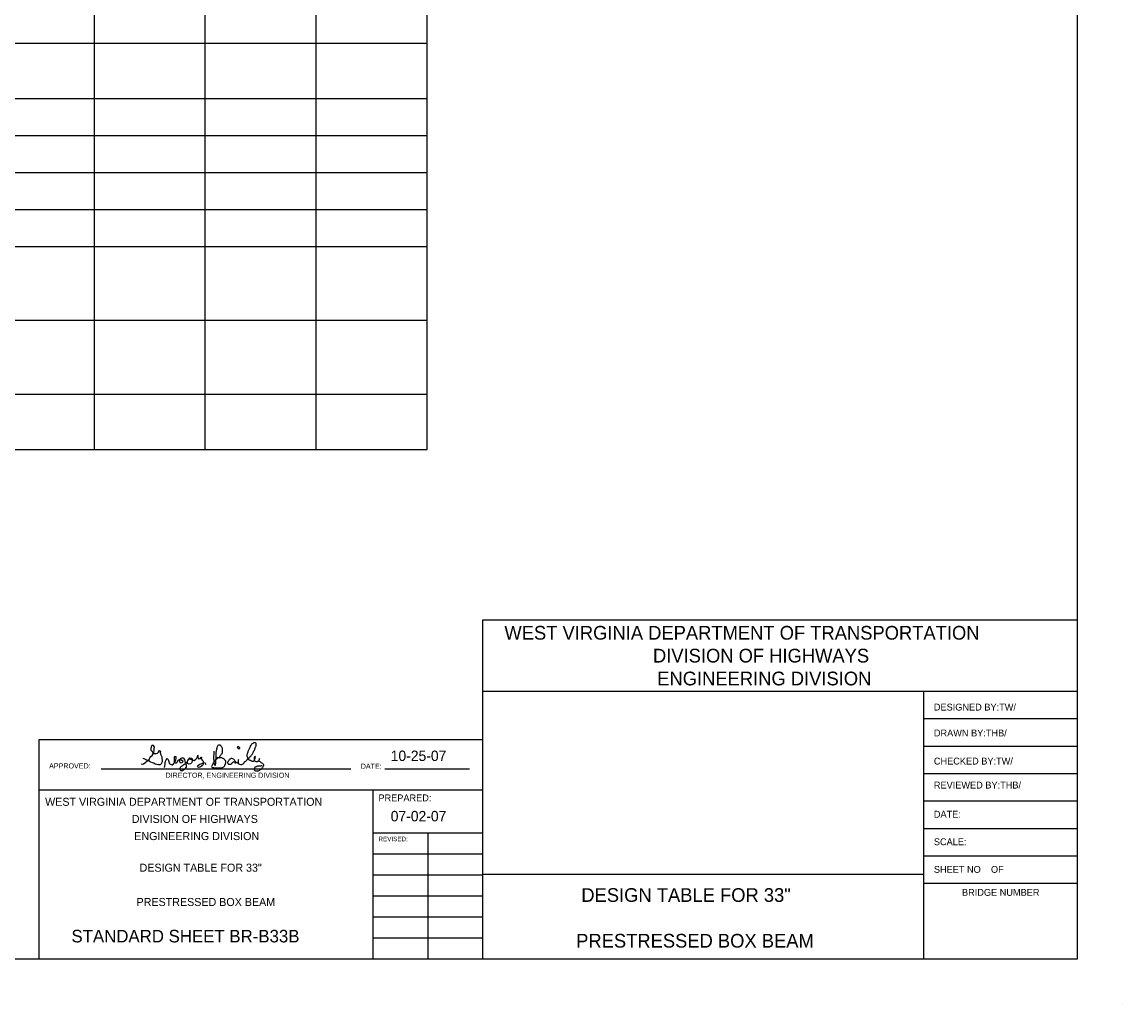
# Model space of a CAD drawing. Extents: x 762.3 to 790.4, y -1210.3 to -1192.2.
# Drawn here: x 780.44 to 790.37, y -1210.35 to -1201.48 of the extents above; entities that cross this region are included whole.
import ezdxf

# ---------------------------------------------------------------- set-up
doc = ezdxf.new("R2010")
doc.units = 0
for name, color, linetype in [('CURBLINE', 7, 'Continuous'), ('Default', 7, 'Continuous'), ('Level 1', 7, 'Continuous')]:
    doc.layers.add(name, color=color, linetype=linetype)

msp = doc.modelspace()

# ---------------------------------------------------------------- linework, layer by layer
at = {"layer": 'CURBLINE'}
msp.add_line((789.9542, -1206.8764), (784.5917, -1206.8755), dxfattribs=at)
at = {"layer": 'Default'}
for p, q in [((789.9542, -1192.6096), (789.9542, -1209.9346)), ((784.0909, -1205.3356), (784.0909, -1193.1689)), ((781.0909, -1205.3356), (781.0909, -1193.6689)), ((782.0909, -1205.3356), (782.0909, -1193.6689)), ((783.0909, -1205.3356), (783.0909, -1193.6689)), ((764.5075, -1201.6689), (784.0909, -1201.6689)), ((764.5075, -1202.1689), (784.0909, -1202.1689)), ((766.2575, -1202.5023), (784.0909, -1202.5023)), ((766.2575, -1202.8356), (784.0909, -1202.8356)), ((764.5075, -1203.1689), (784.0909, -1203.1689)), ((766.2575, -1203.5023), (784.0909, -1203.5023)), ((766.2575, -1204.1689), (784.0909, -1204.1689)), ((764.5075, -1204.8356), (784.0909, -1204.8356)), ((764.5075, -1205.3356), (784.0909, -1205.3356)), ((784.5917, -1206.8755), (784.5917, -1209.9346)), ((788.5682, -1207.519), (784.5917, -1207.519)), ((788.5682, -1207.519), (788.5682, -1209.9346)), ((789.9542, -1207.519), (788.5682, -1207.519)), ((789.9542, -1207.7665), (788.5682, -1207.7665)), ((784.5917, -1207.9546), (780.5905, -1207.9546)), ((780.5905, -1207.9546), (780.5905, -1209.9346)), ((789.9542, -1208.014), (788.5682, -1208.014)), ((781.152, -1208.2157), (783.4022, -1208.2157)), ((783.7105, -1208.2157), (784.4725, -1208.2157)), ((789.9542, -1208.2615), (788.5682, -1208.2615)), ((783.6017, -1208.4083), (780.5905, -1208.4083)), ((783.6017, -1208.4083), (783.6017, -1209.9346)), ((784.5917, -1208.4083), (783.6017, -1208.4083)), ((789.9542, -1208.509), (788.5682, -1208.509)), ((784.5917, -1208.7961), (783.6017, -1208.7961)), ((784.0967, -1208.7961), (784.0967, -1209.9346)), ((789.9542, -1208.7565), (788.5682, -1208.7565)), ((784.5917, -1208.9858), (783.6017, -1208.9858)), ((789.9542, -1209.004), (788.5682, -1209.004)), ((784.5917, -1209.1756), (783.6017, -1209.1756)), ((788.5682, -1209.169), (784.5917, -1209.169)), ((789.9542, -1209.2515), (788.5682, -1209.2515)), ((784.5917, -1209.3653), (783.6017, -1209.3653)), ((784.5917, -1209.5551), (783.6017, -1209.5551)), ((784.5917, -1209.7448), (783.6017, -1209.7448)), ((789.9542, -1209.9346), (763.5542, -1209.9346)), ((790.3667, -1210.3471), (790.3667, -1210.3471))]:
    msp.add_line(p, q, dxfattribs=at)
at = {"layer": 'Level 1'}
for points in [[(781.5129, -1208.1703), (781.528, -1208.1728), (781.5377, -1208.1681), (781.5506, -1208.1603), (781.5606, -1208.1502), (781.5732, -1208.1427), (781.5845, -1208.1314), (781.5908, -1208.1163), (781.5996, -1208.105), (781.6109, -1208.0949), (781.6197, -1208.0824), (781.626, -1208.0686), (781.6285, -1208.0522), (781.631, -1208.0372), (781.6322, -1208.0221), (781.6234, -1208.007), (781.6096, -1208.007), (781.6021, -1208.0183), (781.5996, -1208.0321), (781.5996, -1208.0472), (781.6096, -1208.0573), (781.6184, -1208.0698), (781.631, -1208.0774), (781.6473, -1208.0786), (781.6611, -1208.0761), (781.6699, -1208.0648), (781.6787, -1208.051), (781.6863, -1208.056), (781.6837, -1208.0698), (781.6875, -1208.0836), (781.6925, -1208.0962), (781.6976, -1208.1088), (781.7001, -1208.1238), (781.7026, -1208.1389), (781.7026, -1208.154), (781.6938, -1208.1703), (781.6837, -1208.1804), (781.6674, -1208.1804), (781.6548, -1208.1769), (781.6398, -1208.1728), (781.6272, -1208.1653), (781.6147, -1208.1621), (781.6008, -1208.1552), (781.587, -1208.1502), (781.5757, -1208.1427), (781.5632, -1208.1377), (781.5506, -1208.1326), (781.5393, -1208.1251), (781.5267, -1208.1226)], [(782.167, -1208.0573), (782.1676, -1208.0642), (782.1676, -1208.0711), (782.1676, -1208.078), (782.1676, -1208.0855), (782.1664, -1208.0924), (782.1651, -1208.0993), (782.1651, -1208.1063), (782.1651, -1208.1132), (782.1651, -1208.1201), (782.1658, -1208.127), (782.1664, -1208.1339), (782.1664, -1208.1408), (782.167, -1208.1477), (782.1683, -1208.1546), (782.1689, -1208.1621), (782.1695, -1208.1691), (782.1714, -1208.176), (782.1758, -1208.181), (782.1796, -1208.1866), (782.1815, -1208.1797), (782.184, -1208.1735), (782.1859, -1208.1665), (782.1865, -1208.1596), (782.1865, -1208.1527), (782.1865, -1208.1458), (782.1871, -1208.1389), (782.1871, -1208.132), (782.1877, -1208.1251), (782.1884, -1208.1182), (782.189, -1208.1113), (782.189, -1208.1044), (782.189, -1208.0975), (782.189, -1208.0906), (782.189, -1208.0836), (782.189, -1208.0767), (782.189, -1208.0698), (782.1896, -1208.0629), (782.1909, -1208.056), (782.1921, -1208.0485), (782.194, -1208.0416), (782.1959, -1208.0347), (782.1965, -1208.0277), (782.1991, -1208.0215), (782.2016, -1208.0152), (782.2041, -1208.0089), (782.2078, -1208.0026), (782.2141, -1208.0001), (782.221, -1208.0007), (782.2279, -1208.0026), (782.2323, -1208.0076), (782.2355, -1208.0139), (782.2392, -1208.0196), (782.2424, -1208.0259), (782.2436, -1208.0328), (782.2443, -1208.0397), (782.2443, -1208.0466), (782.2443, -1208.0535), (782.2443, -1208.0604), (782.2443, -1208.0673), (782.243, -1208.0742), (782.2392, -1208.0799), (782.2342, -1208.0843), (782.2298, -1208.0893), (782.2273, -1208.0956), (782.2235, -1208.1012), (782.2198, -1208.1069), (782.2173, -1208.1132), (782.2116, -1208.1169), (782.2053, -1208.1201), (782.1997, -1208.1245), (782.1934, -1208.1282), (782.1884, -1208.1326), (782.1833, -1208.1377), (782.1796, -1208.1433), (782.1746, -1208.1477), (782.1708, -1208.1534), (782.167, -1208.159), (782.162, -1208.1647), (782.1582, -1208.1703), (782.1557, -1208.1766), (782.1519, -1208.1822), (782.1494, -1208.1885), (782.1482, -1208.1954), (782.1507, -1208.2017), (782.157, -1208.2042), (782.1639, -1208.2049), (782.1708, -1208.2067), (782.1777, -1208.208), (782.1846, -1208.2086), (782.1915, -1208.2086), (782.1991, -1208.2086), (782.206, -1208.2086), (782.2129, -1208.2086), (782.2198, -1208.2086), (782.2267, -1208.2086), (782.2336, -1208.2086), (782.2405, -1208.2086), (782.2455, -1208.2036), (782.2518, -1208.2011), (782.2575, -1208.1973), (782.2631, -1208.1923), (782.2656, -1208.186), (782.2681, -1208.1797), (782.2719, -1208.1741), (782.2744, -1208.1678), (782.2763, -1208.1609), (782.2776, -1208.154), (782.2776, -1208.1471), (782.2732, -1208.142), (782.2681, -1208.1377), (782.2631, -1208.1326), (782.2587, -1208.127), (782.2524, -1208.1232), (782.2462, -1208.1194), (782.2392, -1208.1182), (782.2323, -1208.1169), (782.2254, -1208.1157), (782.2179, -1208.1157), (782.2104, -1208.1157), (782.2034, -1208.1157), (782.1965, -1208.1144), (782.1965, -1208.1144)], [(782.3824, -1208.0208), (782.3824, -1208.0277), (782.3875, -1208.0321), (782.3944, -1208.034), (782.4013, -1208.0334), (782.4025, -1208.0265), (782.3975, -1208.0221), (782.3925, -1208.0171), (782.3856, -1208.0171), (782.3793, -1208.0196), (782.3793, -1208.024)], [(782.4829, -1208.1238), (782.4867, -1208.1182), (782.4905, -1208.1125), (782.4942, -1208.1069), (782.4986, -1208.1019), (782.5043, -1208.0981), (782.5087, -1208.0931), (782.5124, -1208.0868), (782.5156, -1208.0805), (782.52, -1208.0742), (782.5238, -1208.0679), (782.5263, -1208.0617), (782.53, -1208.0548), (782.5332, -1208.0478), (782.5363, -1208.0409), (782.5388, -1208.0347), (782.5413, -1208.0284), (782.5438, -1208.0221), (782.5457, -1208.0152), (782.5482, -1208.0089), (782.5495, -1208.002), (782.5508, -1207.9951), (782.5495, -1207.9882), (782.5451, -1207.9832), (782.5388, -1207.9806), (782.5319, -1207.9794), (782.5256, -1207.9832), (782.52, -1207.9869), (782.5137, -1207.9894), (782.5087, -1207.9938), (782.5049, -1207.9995), (782.5011, -1208.0051), (782.4961, -1208.0102), (782.4949, -1208.0171), (782.4923, -1208.0233), (782.4898, -1208.0296), (782.4861, -1208.0353), (782.4836, -1208.0416), (782.4798, -1208.0472), (782.4785, -1208.0541), (782.4748, -1208.0598), (782.4735, -1208.0667), (782.471, -1208.0736), (782.4685, -1208.0805), (782.466, -1208.0868), (782.466, -1208.0937), (782.466, -1208.1006), (782.4672, -1208.1075), (782.4704, -1208.1138), (782.4729, -1208.1207), (782.476, -1208.127), (782.481, -1208.1314), (782.4873, -1208.1339), (782.493, -1208.1383), (782.4999, -1208.1395), (782.5062, -1208.1433), (782.5124, -1208.1458), (782.52, -1208.1464), (782.5269, -1208.1464), (782.5307, -1208.1408), (782.5344, -1208.1351), (782.5376, -1208.1282), (782.5401, -1208.1213), (782.5407, -1208.1144), (782.5426, -1208.1069), (782.5376, -1208.1025), (782.5351, -1208.1094), (782.5325, -1208.1157), (782.5325, -1208.1226), (782.5325, -1208.1295), (782.5325, -1208.1364), (782.5351, -1208.1433), (782.5413, -1208.1471), (782.5476, -1208.1496), (782.5545, -1208.1502), (782.5614, -1208.1502), (782.5677, -1208.1477), (782.5715, -1208.1414), (782.5759, -1208.1364), (782.579, -1208.1295), (782.5809, -1208.1226), (782.5778, -1208.1295), (782.5753, -1208.1358), (782.5727, -1208.142), (782.5753, -1208.1483), (782.5815, -1208.1515), (782.5878, -1208.1546), (782.5922, -1208.1596), (782.5991, -1208.1615), (782.606, -1208.164), (782.6104, -1208.1691), (782.6129, -1208.1753), (782.6154, -1208.1816), (782.6154, -1208.1885), (782.6142, -1208.1954), (782.6092, -1208.1998), (782.6054, -1208.2055), (782.6004, -1208.2111), (782.5966, -1208.2168), (782.5903, -1208.2212), (782.5853, -1208.2256), (782.579, -1208.2293), (782.5727, -1208.2331), (782.5671, -1208.2369), (782.5596, -1208.2375), (782.5526, -1208.2381), (782.5457, -1208.2381), (782.5395, -1208.2344), (782.5357, -1208.2287), (782.5344, -1208.2218), (782.5351, -1208.2149), (782.5369, -1208.208), (782.5407, -1208.2017), (782.5451, -1208.1967), (782.5514, -1208.1942), (782.5577, -1208.1917), (782.5646, -1208.1904), (782.5715, -1208.1904), (782.5784, -1208.1892), (782.5853, -1208.1892), (782.5922, -1208.1879), (782.5991, -1208.1866), (782.6029, -1208.1854)], [(781.723, -1208.2042), (781.7268, -1208.1898), (781.7286, -1208.176), (781.7305, -1208.1621), (781.733, -1208.1483), (781.7381, -1208.1345), (781.7462, -1208.1232), (781.7569, -1208.1314), (781.7632, -1208.1502), (781.7657, -1208.164), (781.7745, -1208.1741), (781.7927, -1208.181), (781.8028, -1208.1716), (781.8115, -1208.1603), (781.8197, -1208.1496), (781.8241, -1208.1364), (781.8291, -1208.1232), (781.8272, -1208.1094), (781.809, -1208.1069), (781.809, -1208.1207), (781.809, -1208.1345), (781.8109, -1208.1483), (781.8159, -1208.1615), (781.8316, -1208.1628), (781.8404, -1208.1527), (781.8448, -1208.1389), (781.8574, -1208.1333), (781.8712, -1208.1333), (781.8869, -1208.1452), (781.8825, -1208.1628), (781.8687, -1208.164), (781.8612, -1208.1527), (781.8618, -1208.1383), (781.8662, -1208.1245), (781.8781, -1208.1182), (781.8919, -1208.1157), (781.9032, -1208.132), (781.907, -1208.1458), (781.9108, -1208.159), (781.9152, -1208.1722), (781.9171, -1208.186), (781.9171, -1208.2005), (781.907, -1208.2174), (781.8963, -1208.2262), (781.8844, -1208.2337), (781.8706, -1208.2344), (781.8649, -1208.2155), (781.8687, -1208.2023), (781.8775, -1208.1923), (781.8872, -1208.1851), (781.8976, -1208.1766), (781.9145, -1208.1665), (781.9284, -1208.1521), (781.9332, -1208.1408), (781.9428, -1208.1282), (781.951, -1208.1176), (781.9692, -1208.1213), (781.9723, -1208.1351), (781.9723, -1208.149), (781.9673, -1208.1621), (781.9566, -1208.1703), (781.9434, -1208.1747), (781.9315, -1208.1684), (781.929, -1208.1552), (781.9321, -1208.142), (781.9403, -1208.1307), (781.9529, -1208.1257), (781.9711, -1208.1339), (781.9893, -1208.1402), (782.005, -1208.1301), (782.0131, -1208.1194), (782.0201, -1208.1069), (782.0251, -1208.0931), (782.0251, -1208.1), (782.0238, -1208.1138), (782.0295, -1208.1263), (782.0458, -1208.122), (782.0546, -1208.1113), (782.0559, -1208.1119), (782.054, -1208.1257), (782.0615, -1208.1383), (782.0716, -1208.1477), (782.0722, -1208.1615), (782.0722, -1208.1753), (782.0646, -1208.1866), (782.0546, -1208.1961), (782.0414, -1208.2017), (782.0282, -1208.2049), (782.0201, -1208.1942), (782.0289, -1208.1822), (782.0408, -1208.1741), (782.0546, -1208.1716), (782.0659, -1208.164), (782.0854, -1208.1603), (782.0954, -1208.176), (782.0967, -1208.1753)], [(782.363, -1208.1697), (782.3642, -1208.1628), (782.3642, -1208.1559), (782.3642, -1208.149), (782.3586, -1208.1439), (782.3536, -1208.1389), (782.3498, -1208.1333), (782.3441, -1208.1295), (782.3385, -1208.1257), (782.3322, -1208.1232), (782.3253, -1208.1232), (782.3184, -1208.1257), (782.3134, -1208.1301), (782.3077, -1208.1345), (782.3027, -1208.1389), (782.2989, -1208.1446), (782.2964, -1208.1508), (782.2926, -1208.1565), (782.2901, -1208.1628), (782.2945, -1208.1678), (782.2989, -1208.1728), (782.3064, -1208.1747), (782.3134, -1208.1747), (782.3203, -1208.1747), (782.3265, -1208.1722), (782.3309, -1208.1665), (782.3353, -1208.1615), (782.3397, -1208.1559), (782.346, -1208.1521), (782.3536, -1208.1521), (782.3611, -1208.1527), (782.3674, -1208.1552), (782.3736, -1208.1578), (782.3793, -1208.1615), (782.3862, -1208.1615), (782.3881, -1208.1546), (782.39, -1208.1477), (782.3906, -1208.1402), (782.3906, -1208.1333), (782.3881, -1208.1395), (782.3868, -1208.1464), (782.3868, -1208.1534), (782.3868, -1208.1603), (782.3875, -1208.1672), (782.3937, -1208.1703), (782.4, -1208.1741), (782.4069, -1208.176), (782.4138, -1208.1766), (782.4208, -1208.1766), (782.4277, -1208.1753), (782.4333, -1208.1716), (782.4371, -1208.1653), (782.4421, -1208.1609), (782.4459, -1208.1546), (782.4509, -1208.1502), (782.4566, -1208.1464), (782.4616, -1208.1414), (782.4666, -1208.1364), (782.4723, -1208.1326), (782.4779, -1208.1289), (782.4817, -1208.1238)]]:
    msp.add_lwpolyline(points, dxfattribs=at)

# ---------------------------------------------------------------- texts
at = {"layer": 'Default'}
for s, height, p in [('WEST VIRGINIA DEPARTMENT OF TRANSPORTATION', 0.12375, (784.7884, -1207.0508)), ('DIVISION OF HIGHWAYS', 0.12375, (786.1282, -1207.2571)), ('ENGINEERING DIVISION', 0.12375, (786.1667, -1207.4633)), ('DESIGNED BY:TW/', 0.061875, (788.6613, -1207.6904)), ('DRAWN BY:THB/', 0.061875, (788.6613, -1207.9241)), ('10-25-07', 0.09375, (783.7631, -1208.1456)), ('CHECKED BY:TW/', 0.061875, (788.6613, -1208.1776)), ('APPROVED:                                                  ', 0.046406, (780.6826, -1208.2129)), ('DATE:', 0.04641, (783.493, -1208.2157)), ('DIRECTOR, ENGINEERING DIVISION', 0.046406, (781.7318, -1208.2974)), ('REVIEWED BY:THB/', 0.061875, (788.6613, -1208.3941)), ('WEST VIRGINIA DEPARTMENT OF TRANSPORTATION', 0.072188, (780.6464, -1208.5498)), ('PREPARED:', 0.06187, (783.6523, -1208.5093)), ('07-02-07', 0.09375, (783.7631, -1208.69)), ('DATE:', 0.06187, (788.6613, -1208.6568)), ('DIVISION OF HIGHWAYS', 0.072188, (781.4279, -1208.7045)), ('ENGINEERING DIVISION', 0.072188, (781.4504, -1208.8592)), ('REVISED:', 0.04125, (783.6523, -1208.8696)), ('SCALE:', 0.06187, (788.6613, -1208.9056)), ('DESIGN TABLE FOR 33"', 0.072188, (781.4981, -1209.1444)), ('SHEET NO    OF', 0.061875, (788.6613, -1209.1545)), ('DESIGN TABLE FOR 33"', 0.12375, (785.482, -1209.4168)), ('BRIDGE NUMBER', 0.061875, (788.9148, -1209.3619)), ('PRESTRESSED BOX BEAM', 0.072188, (781.4711, -1209.4538)), ('STANDARD SHEET BR-B33B', 0.113437, (780.8837, -1209.7825)), ('PRESTRESSED BOX BEAM', 0.12375, (785.4357, -1209.8293))]:
    msp.add_text(s, height=height, dxfattribs=at).set_placement(p)

doc.saveas('drawing.dxf')
